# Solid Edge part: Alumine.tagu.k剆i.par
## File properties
Author: Türk
Template: Iso Part.par
Last saved by: Türk
Revision: 2
Application: Solid Edge
Accuracy: 0,990
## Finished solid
Body 1: solid body, 18 faces, 31 edges, 14 vertices.
  Faces by surface: cylinder 12, plane 4, torus 2
  Edges by curve: circle 12, intersection 10, ellipse 7, line 2
Bounding box of the edges (mm; curved faces can reach further): 300.000 x 118.000 x 50.000, from (-275, 0, -25) to (25, 118, 25).
Cylindrical faces by radius (mm): R10.5 x2, R15 x8, R25 x2
Toroidal faces (ring radius, tube radius in mm): R400 r15 x2
Planar faces by outward normal: +y 2, -y 2
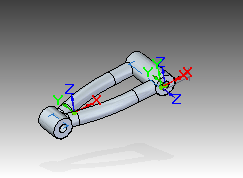
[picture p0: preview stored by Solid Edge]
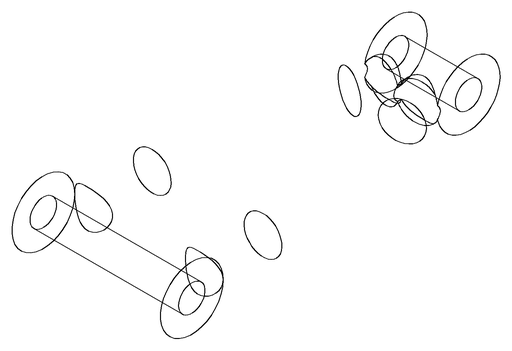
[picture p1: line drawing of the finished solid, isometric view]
